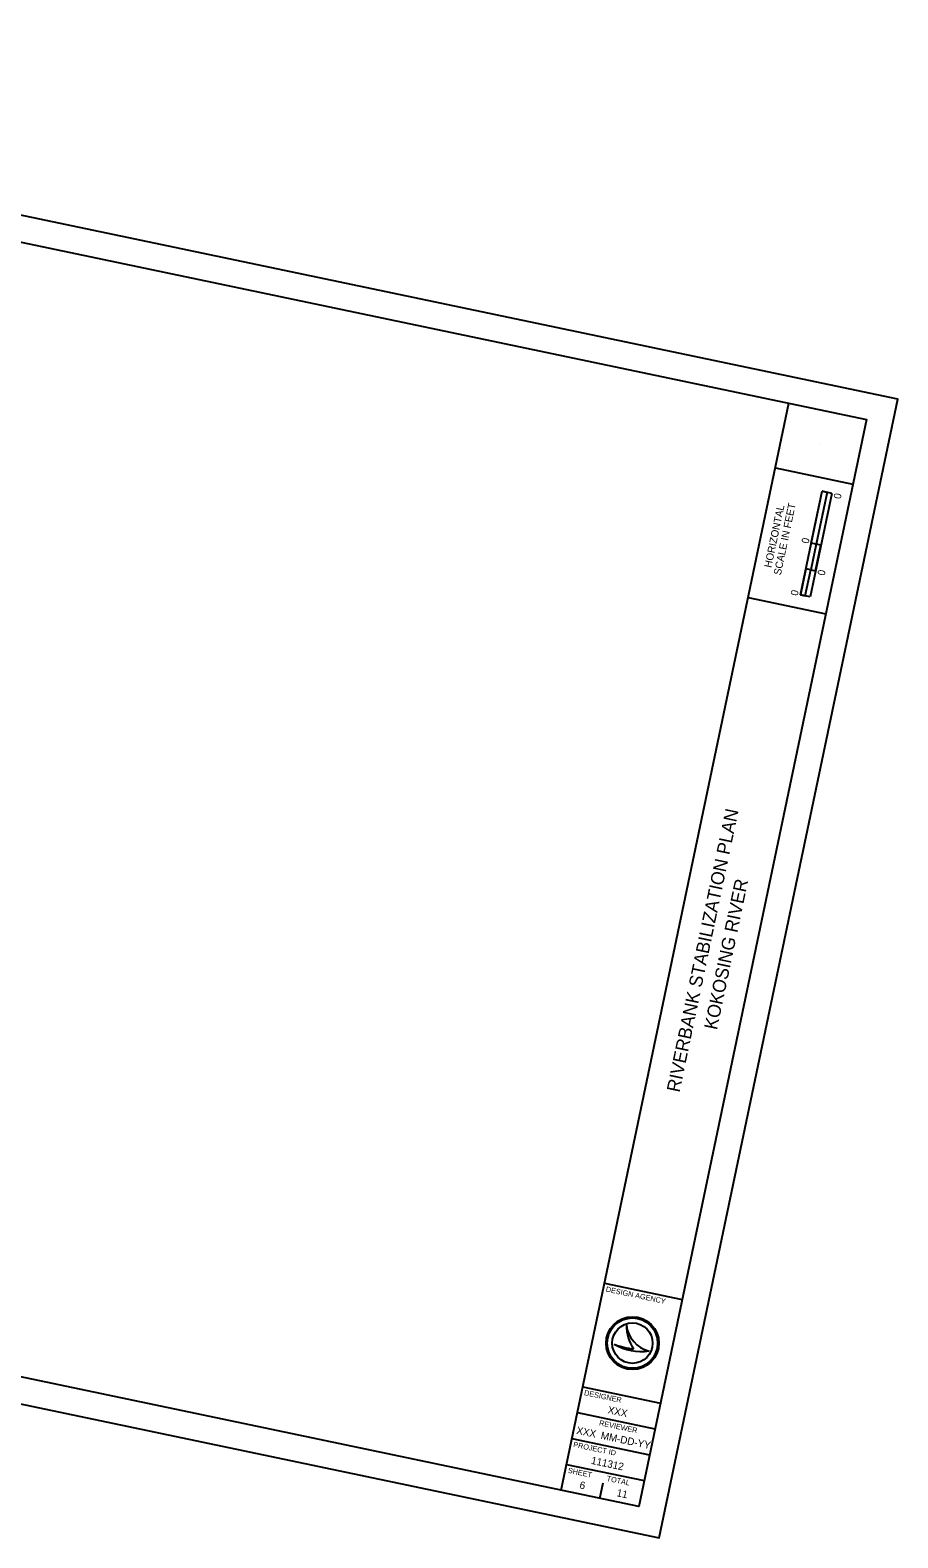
# Model space of a CAD drawing. Extents: x 2001324 to 2002458, y 252301 to 253250.
# Drawn here: x 2001966 to 2002458, y 252395 to 253250 of the extents above; entities that cross this region are included whole.
import ezdxf

# ---------------------------------------------------------------- set-up
doc = ezdxf.new("R2010")
doc.units = 0
for name, color, linetype in [('_CIVIL_CONSTRUCTION', 7, 'Continuous'), ('Default', 7, 'Continuous'), ('GE_P_Alignment', 7, 'Continuous'), ('SC_Scratch1', 7, 'Continuous')]:
    doc.layers.add(name, color=color, linetype=linetype)

msp = doc.modelspace()

# ---------------------------------------------------------------- linework, layer by layer
at = {"layer": '_CIVIL_CONSTRUCTION'}
msp.add_lwpolyline([(2001324.45, 252603.98), (2002322.74, 252394.68), (2002458.17, 253040.64), (2001459.87, 253249.94)], close=True, dxfattribs=at)
at = {"layer": 'GE_P_Alignment'}
for p, q in [((2002414.54, 253015.3), (2002414.54, 253015.3)), ((2002402.91, 252929.61), (2002415.22, 252988.34)), ((2002420.73, 252987.18), (2002408.42, 252928.46)), ((2002409.07, 252958.97), (2002415.22, 252988.34)), ((2002417.99, 252987.76), (2002411.83, 252958.39)), ((2002420.73, 252987.18), (2002415.22, 252988.34)), ((2002415.22, 252988.34), (2002417.96, 252987.76)), ((2002417.96, 252987.76), (2002417.99, 252987.76)), ((2002411.83, 252958.39), (2002409.07, 252958.97)), ((2002411.81, 252958.4), (2002408.73, 252943.72)), ((2002411.47, 252943.14), (2002414.55, 252957.83)), ((2002414.55, 252957.83), (2002411.81, 252958.4)), ((2002405.99, 252944.29), (2002402.91, 252929.61)), ((2002405.65, 252929.04), (2002408.73, 252943.72)), ((2002408.73, 252943.72), (2002405.99, 252944.29)), ((2002408.73, 252943.72), (2002411.47, 252943.14)), ((2002408.42, 252928.46), (2002402.91, 252929.61)), ((2002402.91, 252929.61), (2002405.65, 252929.04)), ((2002304.13, 252515.35), (2002304.13, 252515.35)), ((2002297.25, 252504.53), (2002297.25, 252504.53)), ((2002307.58, 252505.14), (2002307.58, 252505.14)), ((2002316.99, 252500.67), (2002316.99, 252500.67)), ((2002279.18, 252424.5), (2002279.18, 252424.5)), ((2002289.12, 252417.06), (2002290.96, 252425.86))]:
    msp.add_line(p, q, dxfattribs=at)
for radius in [15, 14.3, 14.3, 11.47]:
    msp.add_circle((2002307.58, 252505.14), radius, dxfattribs=at)
for centre, radius, start, end in [((2002321.39, 252517.5), 17.4, 187.08478, 187.09105), ((2002328, 252515.27), 23.87, 179.79703, 179.80125), ((2002321.39, 252517.5), 17.4, 187.09105, 255.32485), ((2002328, 252515.27), 23.87, 179.80125, 214.25378), ((2002311.69, 252539.66), 37.98, 247.6555, 247.65863), ((2002312.63, 252530.75), 30.39, 239.61185, 239.61675), ((2002312.63, 252530.75), 30.39, 239.61675, 278.24235), ((2002311.69, 252539.66), 37.98, 247.65863, 264.82633)]:
    msp.add_arc(centre, radius, start, end, dxfattribs=at)
at = {"layer": 'SC_Scratch1'}
for p, q in [((2002267.1, 252421.67), (2002396.37, 253038.27)), ((2002388.67, 253001.57), (2002432.72, 252992.33)), ((2002373.28, 252928.16), (2002417.33, 252918.93)), ((2002291.72, 252539.12), (2002335.76, 252529.89)), ((2002279.41, 252480.4), (2002323.45, 252471.16)), ((2002276.33, 252465.72), (2002320.37, 252456.48)), ((2002273.25, 252451.03), (2002317.29, 252441.8)), ((2002270.17, 252436.35), (2002314.22, 252427.12))]:
    msp.add_line(p, q, dxfattribs=at)
msp.add_lwpolyline([(2001500.84, 253226.02), (2002440.41, 253029.03), (2002311.14, 252412.44), (2001371.57, 252609.43)], close=True, dxfattribs=at)

# ---------------------------------------------------------------- texts
at = {"layer": 'Default'}
for s, height, rotation, p in [('0', 4.2, 78.15911, (2002425.71, 252983.71)), ('0', 4.2, 78.15911, (2002407.53, 252958.4)), ('0', 4.2, 78.15911, (2002416.6, 252940.26)), ('RIVERBANK STABILIZATION PLAN', 7.5, 78.15911, (2002334.27, 252647.03)), ('KOKOSING RIVER ', 7.5, 78.15911, (2002355.49, 252682.48)), ('XXX', 4.2, 348.15911, (2002293.27, 252465.38)), ('XXX', 4.2, 348.15911, (2002275.51, 252453.78)), ('MM-DD-YY', 4.2, 348.15911, (2002289.34, 252450.88)), ('111312', 4.2, 348.15911, (2002283.84, 252436.71)), ('6', 4.2, 348.15911, (2002277.29, 252422.76)), ('11', 4.2, 348.15911, (2002298.32, 252418.34))]:
    msp.add_text(s, height=height, rotation=rotation, dxfattribs=at).set_placement(p)
at = {"layer": 'GE_P_Alignment'}
for s, height, rotation, p in [('HORIZONTAL', 4.2, 78.15911, (2002386.41, 252944.73)), ('SCALE IN FEET', 4.2, 78.15911, (2002391.74, 252940.51)), ('0', 4.2, 78.15911, (2002401.33, 252928.83)), ('DESIGN AGENCY', 3, 348.15911, (2002292.26, 252534.41)), ('DESIGNER', 3, 348.15911, (2002279.95, 252475.68)), ('REVIEWER', 3, 348.15911, (2002288.48, 252458.57)), ('PROJECT ID', 3, 348.15911, (2002273.8, 252446.32)), ('SHEET', 3, 348.15911, (2002270.72, 252431.64)), ('TOTAL', 3, 348.15911, (2002292.74, 252427.03))]:
    msp.add_text(s, height=height, rotation=rotation, dxfattribs=at).set_placement(p)

doc.saveas('drawing.dxf')
